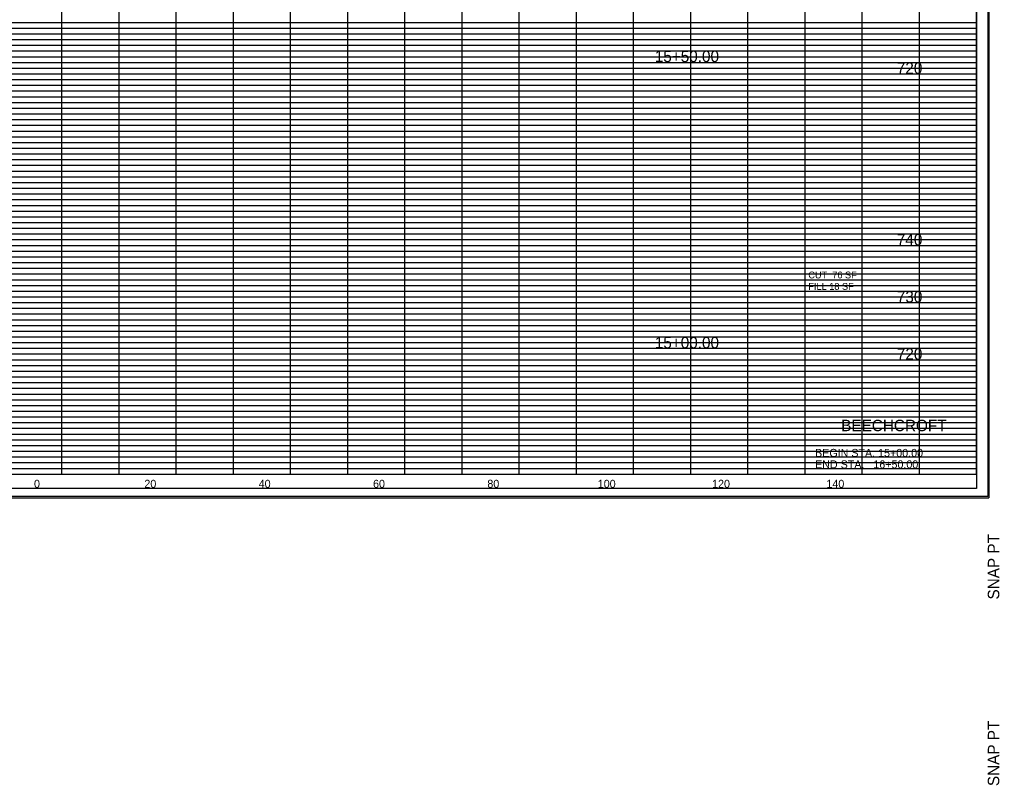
# Model space of a CAD drawing. Extents: x -200 to 1704, y -325 to 2307.
# Drawn here: x 1152.6 to 1324, y 1485.5 to 1619.5 of the extents above; entities that cross this region are included whole.
import ezdxf

# ---------------------------------------------------------------- set-up
doc = ezdxf.new("R2010")
doc.units = 0
for name, color, linetype in [('DESIGN - SHEET - Corner Text', 7, 'Continuous'), ('DESIGN - SHEET - Light Grid', 7, 'Continuous'), ('DESIGN - SHEET - Linework', 7, 'Continuous'), ('DESIGN - SHEET - Plot Shape', 7, 'Continuous'), ('DESIGN - TYPICAL - Text', 7, 'Continuous')]:
    doc.layers.add(name, color=color, linetype=linetype)

msp = doc.modelspace()

# ---------------------------------------------------------------- linework, layer by layer
at = {"layer": 'DESIGN - SHEET - Light Grid'}
for p, q in [((1080, 1619), (1160, 1619)), ((1160, 1619), (1240, 1619)), ((1240, 1619), (1320, 1619)), ((1080, 1618), (1160, 1618)), ((1080, 1617), (1160, 1617)), ((1160, 1618), (1240, 1618)), ((1160, 1617), (1240, 1617)), ((1240, 1618), (1320, 1618)), ((1240, 1617), (1320, 1617)), ((1080, 1616), (1160, 1616)), ((1080, 1615), (1160, 1615)), ((1160, 1616), (1240, 1616)), ((1160, 1615), (1240, 1615)), ((1240, 1616), (1320, 1616)), ((1240, 1615), (1320, 1615)), ((1080, 1614), (1160, 1614)), ((1080, 1613), (1160, 1613)), ((1160, 1614), (1240, 1614)), ((1160, 1613), (1240, 1613)), ((1240, 1614), (1320, 1614)), ((1240, 1613), (1320, 1613)), ((1080, 1612), (1160, 1612)), ((1160, 1612), (1240, 1612)), ((1240, 1612), (1320, 1612)), ((1080, 1611), (1160, 1611)), ((1160, 1611), (1240, 1611)), ((1240, 1611), (1320, 1611)), ((1080, 1609), (1160, 1609)), ((1080, 1608), (1160, 1608)), ((1160, 1609), (1240, 1609)), ((1160, 1608), (1240, 1608)), ((1240, 1609), (1320, 1609)), ((1240, 1608), (1320, 1608)), ((1080, 1607), (1160, 1607)), ((1160, 1607), (1240, 1607)), ((1240, 1607), (1320, 1607)), ((1080, 1606), (1160, 1606)), ((1080, 1605), (1160, 1605)), ((1160, 1606), (1240, 1606)), ((1160, 1605), (1240, 1605)), ((1240, 1606), (1320, 1606)), ((1240, 1605), (1320, 1605)), ((1080, 1604), (1160, 1604)), ((1080, 1603), (1160, 1603)), ((1160, 1604), (1240, 1604)), ((1160, 1603), (1240, 1603)), ((1240, 1604), (1320, 1604)), ((1240, 1603), (1320, 1603)), ((1080, 1602), (1160, 1602)), ((1080, 1601), (1160, 1601)), ((1160, 1602), (1240, 1602)), ((1160, 1601), (1240, 1601)), ((1240, 1602), (1320, 1602)), ((1240, 1601), (1320, 1601)), ((1080, 1599), (1160, 1599)), ((1080, 1598), (1160, 1598)), ((1160, 1599), (1240, 1599)), ((1160, 1598), (1240, 1598)), ((1240, 1599), (1320, 1599)), ((1240, 1598), (1320, 1598)), ((1080, 1597), (1160, 1597)), ((1080, 1596), (1160, 1596)), ((1160, 1597), (1240, 1597)), ((1160, 1596), (1240, 1596)), ((1240, 1597), (1320, 1597)), ((1240, 1596), (1320, 1596)), ((1080, 1595), (1160, 1595)), ((1160, 1595), (1240, 1595)), ((1240, 1595), (1320, 1595)), ((1080, 1594), (1160, 1594)), ((1080, 1593), (1160, 1593)), ((1160, 1594), (1240, 1594)), ((1160, 1593), (1240, 1593)), ((1240, 1594), (1320, 1594)), ((1240, 1593), (1320, 1593)), ((1080, 1592), (1160, 1592)), ((1080, 1591), (1160, 1591)), ((1160, 1592), (1240, 1592)), ((1160, 1591), (1240, 1591)), ((1240, 1592), (1320, 1592)), ((1240, 1591), (1320, 1591)), ((1080, 1589), (1160, 1589)), ((1160, 1589), (1240, 1589)), ((1240, 1589), (1320, 1589)), ((1080, 1588), (1160, 1588)), ((1160, 1588), (1240, 1588)), ((1240, 1588), (1320, 1588)), ((1080, 1587), (1160, 1587)), ((1080, 1586), (1160, 1586)), ((1160, 1587), (1240, 1587)), ((1160, 1586), (1240, 1586)), ((1240, 1587), (1320, 1587)), ((1240, 1586), (1320, 1586)), ((1080, 1585), (1160, 1585)), ((1080, 1584), (1160, 1584)), ((1160, 1585), (1240, 1585)), ((1160, 1584), (1240, 1584)), ((1240, 1585), (1320, 1585)), ((1240, 1584), (1320, 1584)), ((1080, 1583), (1160, 1583)), ((1160, 1583), (1240, 1583)), ((1240, 1583), (1320, 1583)), ((1080, 1582), (1160, 1582)), ((1080, 1581), (1160, 1581)), ((1160, 1582), (1240, 1582)), ((1160, 1581), (1240, 1581)), ((1240, 1582), (1320, 1582)), ((1240, 1581), (1320, 1581)), ((1080, 1579), (1160, 1579)), ((1160, 1579), (1240, 1579)), ((1240, 1579), (1320, 1579)), ((1080, 1578), (1160, 1578)), ((1080, 1577), (1160, 1577)), ((1160, 1578), (1240, 1578)), ((1160, 1577), (1240, 1577)), ((1240, 1578), (1320, 1578)), ((1240, 1577), (1320, 1577)), ((1080, 1576), (1160, 1576)), ((1160, 1576), (1240, 1576)), ((1240, 1576), (1320, 1576)), ((1080, 1575), (1160, 1575)), ((1080, 1574), (1160, 1574)), ((1160, 1575), (1240, 1575)), ((1160, 1574), (1240, 1574)), ((1240, 1575), (1320, 1575)), ((1240, 1574), (1320, 1574)), ((1080, 1573), (1160, 1573)), ((1080, 1572), (1160, 1572)), ((1160, 1573), (1240, 1573)), ((1160, 1572), (1240, 1572)), ((1240, 1573), (1320, 1573)), ((1240, 1572), (1320, 1572)), ((1080, 1571), (1160, 1571)), ((1160, 1571), (1240, 1571)), ((1240, 1571), (1320, 1571)), ((1080, 1569), (1160, 1569)), ((1160, 1569), (1240, 1569)), ((1240, 1569), (1320, 1569)), ((1080, 1568), (1160, 1568)), ((1080, 1567), (1160, 1567)), ((1160, 1568), (1240, 1568)), ((1160, 1567), (1240, 1567)), ((1240, 1568), (1320, 1568)), ((1240, 1567), (1320, 1567)), ((1080, 1566), (1160, 1566)), ((1080, 1565), (1160, 1565)), ((1160, 1566), (1240, 1566)), ((1160, 1565), (1240, 1565)), ((1240, 1566), (1320, 1566)), ((1240, 1565), (1320, 1565)), ((1080, 1564), (1160, 1564)), ((1160, 1564), (1240, 1564)), ((1240, 1564), (1320, 1564)), ((1080, 1563), (1160, 1563)), ((1080, 1562), (1160, 1562)), ((1160, 1563), (1240, 1563)), ((1160, 1562), (1240, 1562)), ((1240, 1563), (1320, 1563)), ((1240, 1562), (1320, 1562)), ((1080, 1561), (1160, 1561)), ((1160, 1561), (1240, 1561)), ((1240, 1561), (1320, 1561)), ((1080, 1559), (1160, 1559)), ((1160, 1559), (1240, 1559)), ((1240, 1559), (1320, 1559)), ((1080, 1558), (1160, 1558)), ((1080, 1557), (1160, 1557)), ((1160, 1558), (1240, 1558)), ((1160, 1557), (1240, 1557)), ((1240, 1558), (1320, 1558)), ((1240, 1557), (1320, 1557)), ((1080, 1556), (1160, 1556)), ((1080, 1555), (1160, 1555)), ((1160, 1556), (1240, 1556)), ((1160, 1555), (1240, 1555)), ((1240, 1556), (1320, 1556)), ((1240, 1555), (1320, 1555)), ((1080, 1554), (1160, 1554)), ((1080, 1553), (1160, 1553)), ((1160, 1554), (1240, 1554)), ((1160, 1553), (1240, 1553)), ((1240, 1554), (1320, 1554)), ((1240, 1553), (1320, 1553)), ((1080, 1552), (1160, 1552)), ((1160, 1552), (1240, 1552)), ((1240, 1552), (1320, 1552)), ((1080, 1551), (1160, 1551)), ((1160, 1551), (1240, 1551)), ((1240, 1551), (1320, 1551)), ((1080, 1549), (1160, 1549)), ((1080, 1548), (1160, 1548)), ((1160, 1549), (1240, 1549)), ((1160, 1548), (1240, 1548)), ((1240, 1549), (1320, 1549)), ((1240, 1548), (1320, 1548)), ((1080, 1547), (1160, 1547)), ((1160, 1547), (1240, 1547)), ((1240, 1547), (1320, 1547)), ((1080, 1546), (1160, 1546)), ((1080, 1545), (1160, 1545)), ((1160, 1546), (1240, 1546)), ((1160, 1545), (1240, 1545)), ((1240, 1546), (1320, 1546)), ((1240, 1545), (1320, 1545)), ((1080, 1544), (1160, 1544)), ((1080, 1543), (1160, 1543)), ((1160, 1544), (1240, 1544)), ((1160, 1543), (1240, 1543)), ((1240, 1544), (1320, 1544)), ((1240, 1543), (1320, 1543)), ((1080, 1542), (1160, 1542)), ((1080, 1541), (1160, 1541)), ((1160, 1542), (1240, 1542)), ((1160, 1541), (1240, 1541)), ((1240, 1542), (1320, 1542)), ((1240, 1541), (1320, 1541))]:
    msp.add_line(p, q, dxfattribs=at)
at = {"layer": 'DESIGN - SHEET - Linework'}
for p, q in [((1322.17, 1754.14), (1322.17, 1535.86)), ((1160, 1540), (1160, 1750)), ((1170, 1540), (1170, 1750)), ((1180, 1540), (1180, 1750)), ((1190, 1540), (1190, 1750)), ((1200, 1540), (1200, 1750)), ((1210, 1540), (1210, 1750)), ((1220, 1540), (1220, 1750)), ((1230, 1540), (1230, 1750)), ((1240, 1540), (1240, 1750)), ((1250, 1540), (1250, 1750)), ((1260, 1540), (1260, 1750)), ((1270, 1540), (1270, 1750)), ((1280, 1540), (1280, 1740)), ((1290, 1540), (1290, 1740)), ((1300, 1540), (1300, 1740)), ((1310, 1540), (1310, 1740)), ((1000, 1610), (1320, 1610)), ((1000, 1600), (1320, 1600)), ((1000, 1590), (1320, 1590)), ((1000, 1580), (1320, 1580)), ((1000, 1570), (1320, 1570)), ((1000, 1560), (1320, 1560)), ((1000, 1550), (1320, 1550)), ((981.77, 1535.86), (1322.17, 1535.86))]:
    msp.add_line(p, q, dxfattribs=at)
msp.add_lwpolyline([(1000, 1750), (1000, 1540), (1320, 1540), (1320, 1750), (1000, 1750)], dxfattribs=at)
at = {"layer": 'DESIGN - SHEET - Plot Shape'}
for points in [[(981.97, 1753.94), (1321.97, 1753.94), (1321.97, 1536.06), (981.97, 1536.06)], [(991.5, 1750), (1320, 1750), (1320, 1537.5), (991.5, 1537.5)]]:
    msp.add_lwpolyline(points, close=True, dxfattribs=at)

# ---------------------------------------------------------------- texts
at = {"layer": 'DESIGN - SHEET - Corner Text'}
for s, height, p in [('BEECHCROFT ', 2, (1296.33, 1547.5)), ('BEGIN STA. 15+00.00', 1.4, (1291.75, 1543)), ('END STA.   16+50.00', 1.4, (1291.75, 1541))]:
    msp.add_text(s, height=height, dxfattribs=at).set_placement(p)
for s, p in [('SNAP PT  ', (1323.97, 1518.06)), ('  SNAP PT', (1323.97, 1483.94))]:
    msp.add_text(s, height=2, rotation=90, dxfattribs=at).set_placement(p)
at = {"layer": 'DESIGN - TYPICAL - Text'}
for s, height, p in [('     15+50.00     ', 2, (1260, 1612.06)), ('     720     ', 2, (1302.34, 1610)), ('     740     ', 2, (1302.34, 1580)), ('CUT  76 SF', 1.2, (1290.57, 1574.22)), ('FILL 18 SF', 1.2, (1290.57, 1572.22)), ('     730     ', 2, (1302.34, 1570)), ('     15+00.00     ', 2, (1260, 1561.99)), ('     720     ', 2, (1302.34, 1560)), ('     0     ', 1.4, (1152.51, 1537.6)), ('     20     ', 1.4, (1171.82, 1537.6)), ('     40     ', 1.4, (1191.82, 1537.6)), ('     60     ', 1.4, (1211.82, 1537.6)), ('     80     ', 1.4, (1231.82, 1537.6)), ('     100     ', 1.4, (1251.14, 1537.6)), ('     120     ', 1.4, (1271.14, 1537.6)), ('     140     ', 1.4, (1291.14, 1537.6))]:
    msp.add_text(s, height=height, dxfattribs=at).set_placement(p)

doc.saveas('drawing.dxf')
